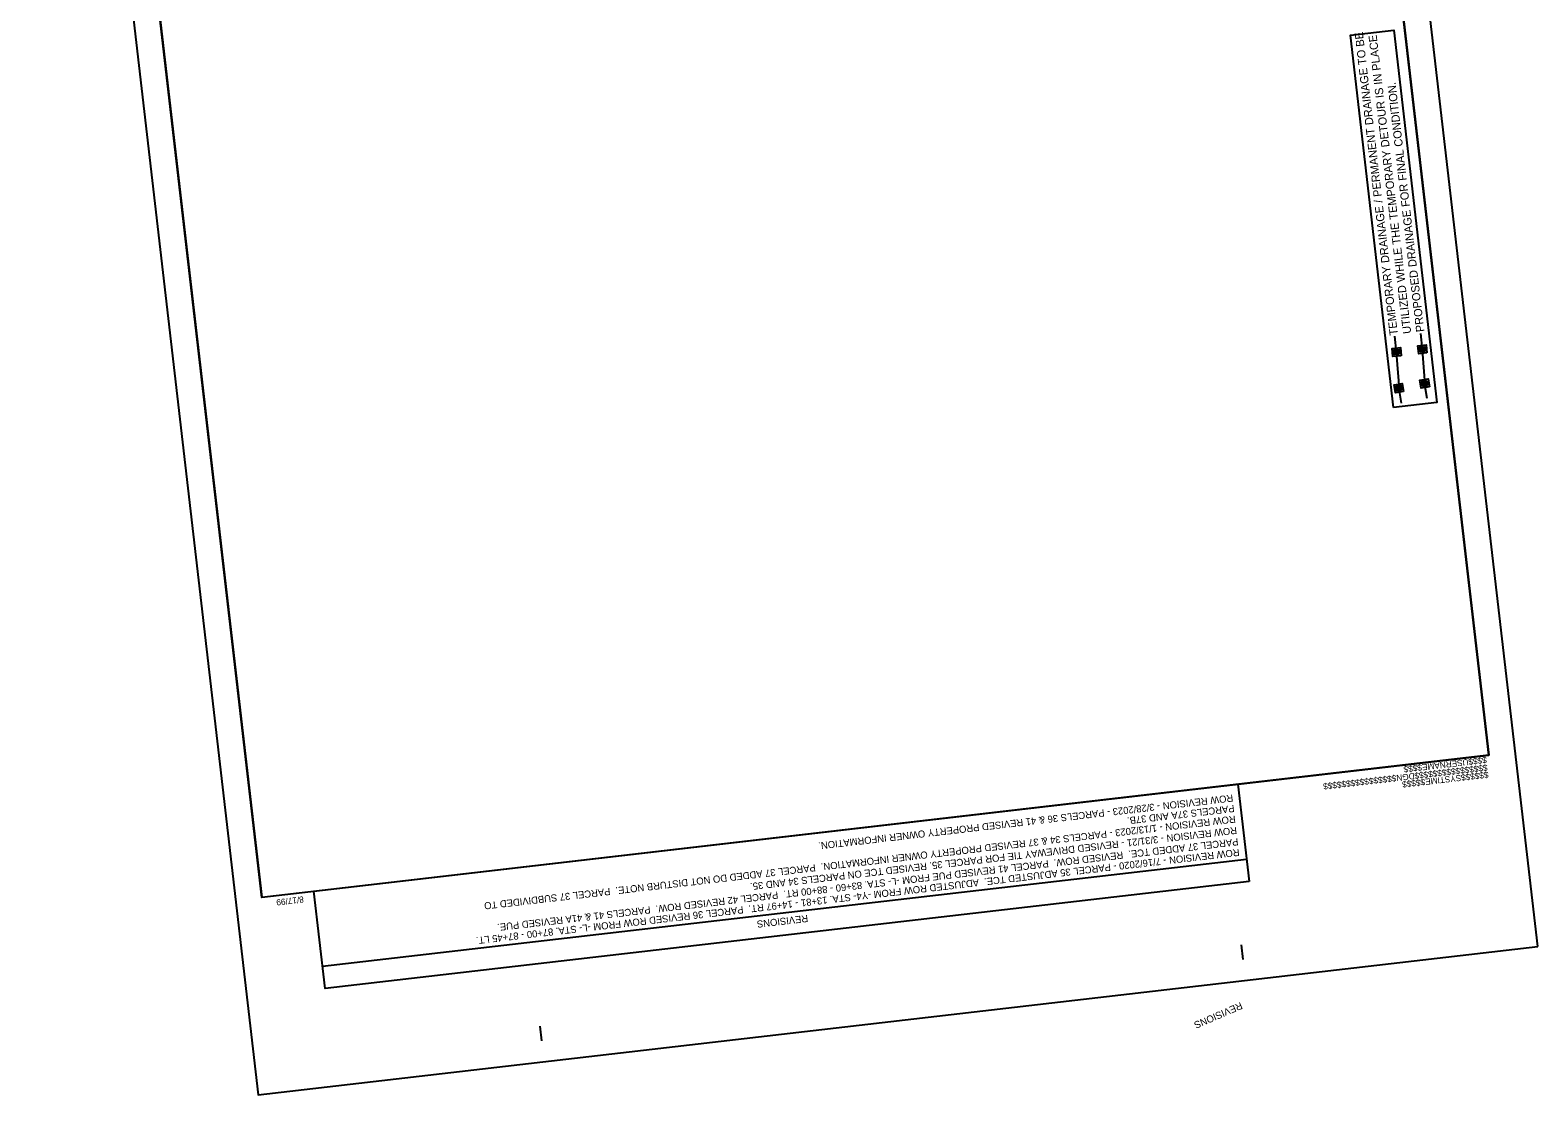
# Model space of a CAD drawing. Extents: x 477709 to 478991, y 494339 to 496137.
# Drawn here: x 477709 to 478991, y 494339 to 495244 of the extents above; entities that cross this region are included whole.
import ezdxf

# ---------------------------------------------------------------- set-up
doc = ezdxf.new("R2010")
doc.units = 0
for name, color, linetype in [('Old_Level_41', 7, 'Continuous'), ('Prop Drainage Structure CELL', 7, 'Continuous'), ('Prop Grid Mask', 7, 'Continuous'), ('Sheet Block Revision CELL', 7, 'Continuous'), ('Sheet Data Field CELL', 7, 'Continuous'), ('Sheet Layout Plan Border', 7, 'Continuous'), ('Sheet Plan CELL', 7, 'Continuous'), ('Sheet Plot Border Outside CELL', 7, 'Continuous')]:
    doc.layers.add(name, color=color, linetype=linetype)

msp = doc.modelspace()

# ---------------------------------------------------------------- linework, layer by layer
at = {"layer": 'Old_Level_41'}
for p, q in [((478892.5, 494972.9), (478891.1, 494986.3)), ((478890.5, 494972.7), (478890.5, 494972.7)), ((478892.4, 494974.1), (478892.4, 494974.1)), ((478892.5, 494972.9), (478892.5, 494972.9)), ((478895.1, 494939.4), (478892.6, 494972.4)), ((478892.7, 494971.7), (478892.7, 494971.7)), ((478894.5, 494973.1), (478894.5, 494973.1)), ((478892.4, 494943.5), (478892.4, 494943.5)), ((478894.2, 494945), (478894.2, 494945)), ((478894.4, 494943.8), (478894.4, 494943.8)), ((478896.4, 494944.2), (478896.4, 494944.2)), ((478894.6, 494942.7), (478894.6, 494942.7)), ((478896.6, 494931), (478895.1, 494939.4))]:
    msp.add_line(p, q, dxfattribs=at)
for points in [[(478896.4, 494969.8), (478889.4, 494969.1), (478888.7, 494976), (478895.6, 494976.8)], [(478894.7, 494971.1), (478890.8, 494970.7), (478890.3, 494974.7), (478894.3, 494975.1)], [(478898.4, 494941), (478891.5, 494939.8), (478890.4, 494946.7), (478897.3, 494947.9)], [(478896.7, 494942.2), (478892.8, 494941.5), (478892.1, 494945.5), (478896, 494946.1)]]:
    msp.add_lwpolyline(points, close=True, dxfattribs=at)
for points in [[(478894.6, 494972), (478890.7, 494971.5), (478890.4, 494973.9), (478894.4, 494974.3), (478894.6, 494972)], [(478894.6, 494972), (478890.7, 494971.6), (478890.5, 494973.8), (478894.3, 494974.2), (478894.6, 494972)], [(478892.6, 494971.8), (478890.7, 494971.6), (478890.5, 494973.8), (478892.4, 494974), (478892.6, 494971.8)], [(478891.5, 494973.4), (478890.6, 494973.3), (478890.6, 494973.6), (478891.4, 494973.7), (478891.5, 494973.4)], [(478891.5, 494973), (478890.7, 494973), (478890.6, 494973.2), (478891.5, 494973.3), (478891.5, 494973)], [(478891.5, 494972.7), (478890.7, 494972.6), (478890.7, 494972.8), (478891.5, 494972.9), (478891.5, 494972.7)], [(478891.6, 494972.3), (478890.8, 494972.2), (478890.7, 494972.5), (478891.6, 494972.5), (478891.6, 494972.3)], [(478891.6, 494972.2), (478890.8, 494972.1), (478890.8, 494971.8), (478891.6, 494971.9), (478891.6, 494972.2)], [(478892.4, 494973.5), (478891.5, 494973.4), (478891.5, 494973.7), (478892.3, 494973.8), (478892.4, 494973.5)], [(478892.4, 494973.1), (478891.6, 494973.1), (478891.6, 494973.3), (478892.4, 494973.4), (478892.4, 494973.1)], [(478892.5, 494972.8), (478891.6, 494972.7), (478891.6, 494972.9), (478892.4, 494973), (478892.5, 494972.8)], [(478892.5, 494972.4), (478891.7, 494972.3), (478891.6, 494972.6), (478892.5, 494972.6), (478892.5, 494972.4)], [(478892.5, 494972.3), (478891.7, 494972.2), (478891.7, 494971.9), (478892.5, 494972), (478892.5, 494972.3)], [(478894.6, 494972), (478892.7, 494971.8), (478892.4, 494974), (478894.3, 494974.2), (478894.6, 494972)], [(478893.4, 494973.6), (478892.6, 494973.5), (478892.5, 494973.8), (478893.4, 494973.9), (478893.4, 494973.6)], [(478893.4, 494973.2), (478892.6, 494973.2), (478892.6, 494973.4), (478893.4, 494973.5), (478893.4, 494973.2)], [(478893.5, 494972.9), (478892.6, 494972.8), (478892.6, 494973), (478893.4, 494973.1), (478893.5, 494972.9)], [(478893.5, 494972.5), (478892.7, 494972.4), (478892.7, 494972.7), (478893.5, 494972.8), (478893.5, 494972.5)], [(478893.6, 494972.1), (478892.7, 494972), (478892.7, 494972.3), (478893.5, 494972.4), (478893.6, 494972.1)], [(478894.3, 494973.7), (478893.5, 494973.6), (478893.4, 494973.9), (478894.3, 494974), (478894.3, 494973.7)], [(478894.3, 494973.3), (478893.5, 494973.3), (478893.5, 494973.5), (478894.3, 494973.6), (478894.3, 494973.3)], [(478894.4, 494973), (478893.6, 494972.9), (478893.5, 494973.1), (478894.4, 494973.2), (478894.4, 494973)], [(478894.4, 494972.6), (478893.6, 494972.5), (478893.6, 494972.8), (478894.4, 494972.8), (478894.4, 494972.6)], [(478894.5, 494972.2), (478893.6, 494972.1), (478893.6, 494972.4), (478894.4, 494972.5), (478894.5, 494972.2)], [(478896.6, 494943), (478892.6, 494942.3), (478892.2, 494944.6), (478896.2, 494945.3), (478896.6, 494943)], [(478896.5, 494943.1), (478892.7, 494942.4), (478892.3, 494944.6), (478896.1, 494945.2), (478896.5, 494943.1)], [(478894.6, 494942.7), (478892.7, 494942.4), (478892.3, 494944.6), (478894.2, 494944.9), (478894.6, 494942.7)], [(478893.3, 494944.3), (478892.5, 494944.1), (478892.4, 494944.4), (478893.2, 494944.6), (478893.3, 494944.3)], [(478893.4, 494943.9), (478892.5, 494943.8), (478892.5, 494944), (478893.3, 494944.2), (478893.4, 494943.9)], [(478893.4, 494943.5), (478892.6, 494943.4), (478892.6, 494943.7), (478893.4, 494943.8), (478893.4, 494943.5)], [(478893.5, 494943.1), (478892.7, 494943), (478892.6, 494943.3), (478893.4, 494943.4), (478893.5, 494943.1)], [(478893.5, 494943), (478892.7, 494942.9), (478892.7, 494942.6), (478893.5, 494942.8), (478893.5, 494943)], [(478894.2, 494944.4), (478893.4, 494944.3), (478893.3, 494944.6), (478894.2, 494944.7), (478894.2, 494944.4)], [(478894.3, 494944.1), (478893.4, 494943.9), (478893.4, 494944.2), (478894.2, 494944.3), (478894.3, 494944.1)], [(478894.3, 494943.7), (478893.5, 494943.5), (478893.5, 494943.8), (478894.3, 494943.9), (478894.3, 494943.7)], [(478894.4, 494943.3), (478893.6, 494943.2), (478893.5, 494943.4), (478894.3, 494943.6), (478894.4, 494943.3)], [(478894.4, 494943.2), (478893.6, 494943), (478893.6, 494942.8), (478894.5, 494942.9), (478894.4, 494943.2)], [(478896.5, 494943.1), (478894.6, 494942.7), (478894.2, 494944.9), (478896.1, 494945.2), (478896.5, 494943.1)], [(478895.2, 494944.6), (478894.4, 494944.5), (478894.3, 494944.7), (478895.2, 494944.9), (478895.2, 494944.6)], [(478895.3, 494944.2), (478894.4, 494944.1), (478894.4, 494944.4), (478895.2, 494944.5), (478895.3, 494944.2)], [(478895.3, 494943.8), (478894.5, 494943.7), (478894.5, 494944), (478895.3, 494944.1), (478895.3, 494943.8)], [(478895.4, 494943.5), (478894.6, 494943.3), (478894.5, 494943.6), (478895.3, 494943.7), (478895.4, 494943.5)], [(478895.5, 494943.1), (478894.6, 494942.9), (478894.6, 494943.2), (478895.4, 494943.4), (478895.5, 494943.1)], [(478896.1, 494944.8), (478895.3, 494944.6), (478895.2, 494944.9), (478896.1, 494945), (478896.1, 494944.8)], [(478896.2, 494944.4), (478895.3, 494944.2), (478895.3, 494944.5), (478896.1, 494944.6), (478896.2, 494944.4)], [(478896.2, 494944), (478895.4, 494943.9), (478895.4, 494944.1), (478896.2, 494944.3), (478896.2, 494944)], [(478896.3, 494943.6), (478895.5, 494943.5), (478895.4, 494943.7), (478896.3, 494943.9), (478896.3, 494943.6)], [(478896.4, 494943.2), (478895.5, 494943.1), (478895.5, 494943.4), (478896.3, 494943.5), (478896.4, 494943.2)]]:
    msp.add_lwpolyline(points, dxfattribs=at)
at = {"layer": 'Prop Drainage Structure CELL'}
for p, q in [((478870.6, 494970.6), (478869.2, 494984)), ((478868.7, 494970.4), (478868.7, 494970.4)), ((478870.5, 494971.7), (478870.5, 494971.7)), ((478870.6, 494970.6), (478870.6, 494970.6)), ((478873.2, 494935.5), (478870.6, 494970.5)), ((478870.8, 494969.4), (478870.8, 494969.4)), ((478872.6, 494970.8), (478872.6, 494970.8)), ((478870.5, 494939.6), (478870.5, 494939.6)), ((478872.3, 494941.1), (478872.3, 494941.1)), ((478872.5, 494940), (478872.5, 494940)), ((478872.7, 494938.8), (478872.7, 494938.8)), ((478874.6, 494927.1), (478873.2, 494935.5)), ((478874.4, 494940.3), (478874.4, 494940.3))]:
    msp.add_line(p, q, dxfattribs=at)
for points in [[(478874.5, 494967.5), (478867.5, 494966.7), (478866.8, 494973.7), (478873.8, 494974.4)], [(478872.8, 494968.8), (478868.9, 494968.4), (478868.4, 494972.4), (478872.4, 494972.8)], [(478876.5, 494937.1), (478869.6, 494935.9), (478868.4, 494942.8), (478875.3, 494944)], [(478874.8, 494938.3), (478870.8, 494937.7), (478870.2, 494941.6), (478874.1, 494942.3)]]:
    msp.add_lwpolyline(points, close=True, dxfattribs=at)
for points in [[(478872.8, 494969.6), (478868.8, 494969.2), (478868.5, 494971.5), (478872.5, 494972), (478872.8, 494969.6)], [(478872.7, 494969.7), (478868.8, 494969.3), (478868.6, 494971.5), (478872.5, 494971.9), (478872.7, 494969.7)], [(478870.7, 494969.5), (478868.8, 494969.3), (478868.6, 494971.5), (478870.5, 494971.7), (478870.7, 494969.5)], [(478869.6, 494971.1), (478868.7, 494971), (478868.7, 494971.3), (478869.5, 494971.4), (478869.6, 494971.1)], [(478869.6, 494970.7), (478868.8, 494970.6), (478868.8, 494970.9), (478869.6, 494971), (478869.6, 494970.7)], [(478869.7, 494970.3), (478868.8, 494970.3), (478868.8, 494970.5), (478869.6, 494970.6), (478869.7, 494970.3)], [(478869.7, 494970), (478868.9, 494969.9), (478868.8, 494970.1), (478869.7, 494970.2), (478869.7, 494970)], [(478869.7, 494969.9), (478868.9, 494969.8), (478868.9, 494969.5), (478869.7, 494969.6), (478869.7, 494969.9)], [(478870.5, 494971.2), (478869.7, 494971.1), (478869.6, 494971.4), (478870.5, 494971.5), (478870.5, 494971.2)], [(478870.5, 494970.8), (478869.7, 494970.7), (478869.7, 494971), (478870.5, 494971.1), (478870.5, 494970.8)], [(478870.6, 494970.4), (478869.7, 494970.4), (478869.7, 494970.6), (478870.5, 494970.7), (478870.6, 494970.4)], [(478870.6, 494970.1), (478869.8, 494970), (478869.7, 494970.2), (478870.6, 494970.3), (478870.6, 494970.1)], [(478870.6, 494969.9), (478869.8, 494969.9), (478869.8, 494969.6), (478870.6, 494969.7), (478870.6, 494969.9)], [(478872.7, 494969.7), (478870.8, 494969.5), (478870.5, 494971.7), (478872.4, 494971.9), (478872.7, 494969.7)], [(478871.5, 494971.3), (478870.7, 494971.2), (478870.6, 494971.5), (478871.5, 494971.6), (478871.5, 494971.3)], [(478871.5, 494970.9), (478870.7, 494970.8), (478870.7, 494971.1), (478871.5, 494971.2), (478871.5, 494970.9)], [(478871.6, 494970.6), (478870.8, 494970.5), (478870.7, 494970.7), (478871.6, 494970.8), (478871.6, 494970.6)], [(478871.6, 494970.2), (478870.8, 494970.1), (478870.8, 494970.4), (478871.6, 494970.4), (478871.6, 494970.2)], [(478871.7, 494969.8), (478870.8, 494969.7), (478870.8, 494970), (478871.6, 494970.1), (478871.7, 494969.8)], [(478872.4, 494971.4), (478871.6, 494971.3), (478871.6, 494971.6), (478872.4, 494971.7), (478872.4, 494971.4)], [(478872.5, 494971), (478871.6, 494970.9), (478871.6, 494971.2), (478872.4, 494971.3), (478872.5, 494971)], [(478872.5, 494970.6), (478871.7, 494970.6), (478871.6, 494970.8), (478872.5, 494970.9), (478872.5, 494970.6)], [(478872.5, 494970.3), (478871.7, 494970.2), (478871.7, 494970.4), (478872.5, 494970.5), (478872.5, 494970.3)], [(478872.6, 494969.9), (478871.7, 494969.8), (478871.7, 494970.1), (478872.5, 494970.2), (478872.6, 494969.9)], [(478874.6, 494939.2), (478870.7, 494938.5), (478870.3, 494940.8), (478874.2, 494941.5), (478874.6, 494939.2)], [(478874.6, 494939.2), (478870.7, 494938.6), (478870.4, 494940.7), (478874.2, 494941.4), (478874.6, 494939.2)], [(478872.6, 494938.9), (478870.7, 494938.6), (478870.4, 494940.7), (478872.3, 494941.1), (478872.6, 494938.9)], [(478871.4, 494940.4), (478870.5, 494940.3), (478870.5, 494940.6), (478871.3, 494940.7), (478871.4, 494940.4)], [(478871.4, 494940.1), (478870.6, 494939.9), (478870.6, 494940.2), (478871.4, 494940.3), (478871.4, 494940.1)], [(478871.5, 494939.7), (478870.7, 494939.5), (478870.6, 494939.8), (478871.4, 494939.9), (478871.5, 494939.7)], [(478871.5, 494939.3), (478870.7, 494939.2), (478870.7, 494939.4), (478871.5, 494939.6), (478871.5, 494939.3)], [(478871.6, 494939.2), (478870.7, 494939), (478870.8, 494938.8), (478871.6, 494938.9), (478871.6, 494939.2)], [(478872.3, 494940.6), (478871.4, 494940.4), (478871.4, 494940.7), (478872.2, 494940.9), (478872.3, 494940.6)], [(478872.3, 494940.2), (478871.5, 494940.1), (478871.5, 494940.3), (478872.3, 494940.5), (478872.3, 494940.2)], [(478872.4, 494939.8), (478871.6, 494939.7), (478871.5, 494940), (478872.3, 494940.1), (478872.4, 494939.8)], [(478872.5, 494939.4), (478871.6, 494939.3), (478871.6, 494939.6), (478872.4, 494939.7), (478872.5, 494939.4)], [(478872.5, 494939.3), (478871.7, 494939.2), (478871.7, 494938.9), (478872.5, 494939.1), (478872.5, 494939.3)], [(478874.5, 494939.2), (478872.7, 494938.9), (478872.3, 494941.1), (478874.2, 494941.4), (478874.5, 494939.2)], [(478873.3, 494940.8), (478872.4, 494940.6), (478872.4, 494940.9), (478873.2, 494941), (478873.3, 494940.8)], [(478873.3, 494940.4), (478872.5, 494940.2), (478872.5, 494940.5), (478873.3, 494940.6), (478873.3, 494940.4)], [(478873.4, 494940), (478872.6, 494939.9), (478872.5, 494940.1), (478873.4, 494940.3), (478873.4, 494940)], [(478873.5, 494939.6), (478872.6, 494939.5), (478872.6, 494939.7), (478873.4, 494939.9), (478873.5, 494939.6)], [(478873.5, 494939.2), (478872.7, 494939.1), (478872.7, 494939.4), (478873.5, 494939.5), (478873.5, 494939.2)], [(478874.2, 494940.9), (478873.4, 494940.8), (478873.3, 494941), (478874.1, 494941.2), (478874.2, 494940.9)], [(478874.2, 494940.5), (478873.4, 494940.4), (478873.4, 494940.7), (478874.2, 494940.8), (478874.2, 494940.5)], [(478874.3, 494940.1), (478873.5, 494940), (478873.4, 494940.3), (478874.3, 494940.4), (478874.3, 494940.1)], [(478874.4, 494939.8), (478873.5, 494939.6), (478873.5, 494939.9), (478874.3, 494940), (478874.4, 494939.8)], [(478874.4, 494939.4), (478873.6, 494939.2), (478873.6, 494939.5), (478874.4, 494939.7), (478874.4, 494939.4)]]:
    msp.add_lwpolyline(points, dxfattribs=at)
at = {"layer": 'Prop Grid Mask'}
msp.add_lwpolyline([(478867.9, 494923.4), (478831.3, 495239.9), (478868.1, 495244.2), (478904.8, 494927.7)], close=True, dxfattribs=at)
at = {"layer": 'Sheet Block Revision CELL'}
msp.add_line((478743.1, 494539.2), (477957.7, 494448.2), dxfattribs=at)
msp.add_lwpolyline([(478745.3, 494520.6), (477959.9, 494429.6), (477950.3, 494512.2), (478735.7, 494603.2)], close=True, dxfattribs=at)
at = {"layer": 'Sheet Layout Plan Border'}
msp.add_lwpolyline([(478949.1, 494627.9), (478796.1, 495948.5), (478716.6, 495939.3), (478594.3, 496053.4), (478083.6, 495972.6), (477905.9, 496017.1), (477928.9, 495818.4), (477756.5, 495798.4), (477906.1, 494507.1)], close=True, dxfattribs=at)
at = {"layer": 'Sheet Plan CELL'}
for p, q in [((478949.1, 494627.9), (478949.1, 494627.9)), ((477906.1, 494507.1), (477906.1, 494507.1)), ((478740.2, 494454.2), (478738.8, 494466.6)), ((478144.2, 494385.1), (478142.7, 494397.6))]:
    msp.add_line(p, q, dxfattribs=at)
for points in [[(477733.5, 495997.1), (477906.1, 494507.1), (478949.1, 494627.9), (478776.5, 496117.9)], [(478949.1, 494627.9), (477906.1, 494507), (477756.5, 495798.4), (477905.5, 495815.7), (477882.5, 496014.4), (478776.5, 496117.9)]]:
    msp.add_lwpolyline(points, close=True, dxfattribs=at)
at = {"layer": 'Sheet Plot Border Outside CELL'}
msp.add_lwpolyline([(478990.6, 494465.1), (478796.9, 496137.4), (477709.2, 496011.4), (477902.9, 494339.1)], close=True, dxfattribs=at)

# ---------------------------------------------------------------- texts
at = {"layer": 'Sheet Block Revision CELL'}
for s, rotation, p in [('ROW REVISION - 3/28/2023 - PARCELS 36 & 41 REVISED PROPERTY OWNER INFORMATION. ', 186.6074, (478731.3, 494594.5)), ('PARCELS 37A AND 37B.', 186.6074, (478732.4, 494585.6)), ('ROW REVISION - 1/13/2023 - PARCELS 34 & 37 REVISED PROPERTY OWNER INFORMATION.  PARCEL 37 ADDED DO NOT DISTURB NOTE.  PARCEL 37 SUBDIVIDED TO ', 186.6074, (478733.4, 494576.6)), ('ROW REVISION - 3/31/21 - REVISED DRIVEWAY TIE FOR PARCEL 35. REVISED TCE ON PARCELS 34 AND 35.', 186.6074, (478734.5, 494567)), ('ROW REVISION - 7/16/2020 - PARCEL 35 ADJUSTED TCE.  ADJUSTED ROW FROM -Y4- STA. 13+81 - 14+97 RT.  PARCEL 36 REVISED ROW FROM -L- STA. 87+00 - 87+45 LT.', 186.6074, (478736.7, 494548.3)), ('PARCEL 37 ADDED TCE.  REVISED ROW.  PARCEL 41 REVISED PUE FROM -L- STA. 83+60 - 88+00 RT.  PARCEL 42 REVISED ROW.  PARCELS 41 & 41A REVISED PUE.', 186.6074, (478735.7, 494557.3)), ('REVISIONS', 186.6074, (478370, 494492.1)), ('REVISIONS', 203.4424, (478737.9, 494418.1))]:
    msp.add_text(s, height=6, rotation=rotation, dxfattribs=at).set_placement(p)
at = {"layer": 'Sheet Data Field CELL'}
for s, p in [('TEMPORARY DRAINAGE / PERMANENT DRAINAGE TO BE ', (478871.7, 494985.2)), ('UTILIZED WHILE THE TEMPORARY DETOUR IS IN PLACE.', (478883, 494986.5)), ('PROPOSED DRAINAGE FOR FINAL CONDITION.', (478894.2, 494988))]:
    msp.add_text(s, height=7, rotation=96.6074, dxfattribs=at).set_placement(p)
at = {"layer": 'Sheet Plan CELL'}
for s, p in [('$$$$USERNAME$$$$', (478946.9, 494626.5)), ('$$$$$$$$$$$$$$$$DGN$$$$$$$$$$$$$$$$', (478947.6, 494620)), ('$$$$$$SYSTIME$$$$$', (478948.4, 494614)), ('8/17/99', (477941.4, 494507.9))]:
    msp.add_text(s, height=5.25, rotation=186.6074, dxfattribs=at).set_placement(p)

doc.saveas('drawing.dxf')
